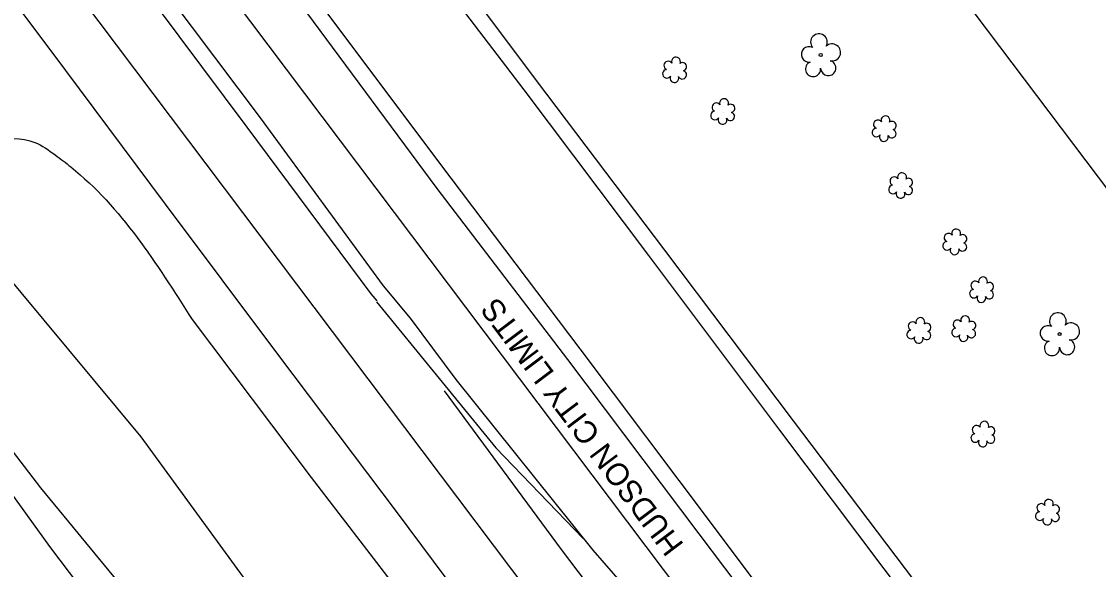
# Model space of a CAD drawing. Extents: x 1262092 to 1264624, y 774970 to 778314.
# Drawn here: x 1264127.3 to 1264367.4, y 775381.8 to 775504 of the extents above; entities that cross this region are included whole.
import ezdxf

# ---------------------------------------------------------------- set-up
doc = ezdxf.new("R2010")
doc.units = 0
for name, color, linetype in [('Exist Boundary City Limits', 7, 'Continuous'), ('Exist Boundary City Limits Text', 7, 'Continuous'), ('Exist Horizontal Alignment', 7, 'Continuous'), ('Exist Horizontal Alignment Tick Large', 7, 'Continuous'), ('Exist Horizontal Alignment Tick Small', 7, 'Continuous'), ('Exist Right of Way Line', 7, 'Continuous'), ('Exist Roads EOP', 7, 'Continuous'), ('Exist Roads EOT', 7, 'Continuous'), ('Exist Utilities Power UG Cable SUE LOS B', 7, 'Continuous'), ('Exist Utilities Telephone UG FO SUE LOS B', 7, 'Continuous'), ('Exist Utilities Water UG Line SUE LOS B', 7, 'Continuous')]:
    doc.layers.add(name, color=color, linetype=linetype)

msp = doc.modelspace()

# ---------------------------------------------------------------- linework, layer by layer
at = {"layer": 'Exist Boundary City Limits'}
msp.add_line((1264481.92, 775101.04), (1263870.58, 775912.68), dxfattribs=at)
at = {"layer": 'Exist Horizontal Alignment'}
msp.add_line((1264460.35, 775084.79), (1262255.05, 778012.66), dxfattribs=at)
at = {"layer": 'Exist Horizontal Alignment Tick Large'}
for p, q in [((1264272.98, 775493.05), (1264272.98, 775493.05)), ((1264283.7, 775483.77), (1264283.7, 775483.77)), ((1264319.7, 775479.94), (1264319.7, 775479.94)), ((1264323.39, 775467.25), (1264323.39, 775467.25)), ((1264335.46, 775454.68), (1264335.46, 775454.68)), ((1264341.43, 775444.01), (1264341.43, 775444.01)), ((1264327.45, 775434.93), (1264327.45, 775434.93)), ((1264337.46, 775435.34), (1264337.46, 775435.34)), ((1264341.73, 775411.81), (1264341.73, 775411.81)), ((1264356.13, 775394.38), (1264356.13, 775394.38))]:
    msp.add_line(p, q, dxfattribs=at)
for centre, radius, start, end in [((1264273.21, 775495.09), 0.99, 334.8391, 200.4717), ((1264271.5, 775494.18), 0.968, 35.8908, 245.4216), ((1264274.65, 775493.92), 0.929, 284.4567, 126.0861), ((1264271.18, 775492.35), 0.955, 95.1099, 327.9534), ((1264272.85, 775491.37), 0.984, 151.2797, 21.387), ((1264274.62, 775492.12), 0.937, 204.9913, 73.4601), ((1264283.93, 775485.81), 0.99, 334.8391, 200.4717), ((1264281.9, 775483.06), 0.955, 95.1099, 327.9534), ((1264282.22, 775484.89), 0.968, 35.8908, 245.4216), ((1264285.38, 775484.63), 0.929, 284.4567, 126.0861), ((1264283.58, 775482.08), 0.984, 151.2797, 21.387), ((1264285.34, 775482.84), 0.937, 204.9913, 73.4601), ((1264318.22, 775481.07), 0.968, 35.8908, 245.4216), ((1264319.93, 775481.98), 0.99, 334.8391, 200.4717), ((1264321.38, 775480.81), 0.929, 284.4567, 126.0861), ((1264317.9, 775479.24), 0.955, 95.1099, 327.9534), ((1264321.34, 775479.01), 0.937, 204.9913, 73.4601), ((1264319.57, 775478.26), 0.984, 151.2797, 21.387), ((1264323.61, 775469.29), 0.99, 334.8391, 200.4717), ((1264321.59, 775466.55), 0.955, 95.1099, 327.9534), ((1264321.9, 775468.38), 0.968, 35.8908, 245.4216), ((1264325.02, 775466.33), 0.937, 204.9913, 73.4601), ((1264325.06, 775468.12), 0.929, 284.4567, 126.0861), ((1264323.26, 775465.57), 0.984, 151.2797, 21.387), ((1264335.69, 775456.72), 0.99, 334.8391, 200.4717), ((1264333.98, 775455.8), 0.968, 35.8908, 245.4216), ((1264337.14, 775455.55), 0.929, 284.4567, 126.0861), ((1264333.66, 775453.97), 0.955, 95.1099, 327.9534), ((1264335.34, 775452.99), 0.984, 151.2797, 21.387), ((1264337.1, 775453.75), 0.937, 204.9913, 73.4601), ((1264339.95, 775445.14), 0.968, 35.8908, 245.4216), ((1264341.66, 775446.05), 0.99, 334.8391, 200.4717), ((1264343.1, 775444.88), 0.929, 284.4567, 126.0861), ((1264339.63, 775443.31), 0.955, 95.1099, 327.9534), ((1264343.07, 775443.08), 0.937, 204.9913, 73.4601), ((1264341.3, 775442.33), 0.984, 151.2797, 21.387), ((1264337.69, 775437.38), 0.99, 334.8391, 200.4717), ((1264325.97, 775436.05), 0.968, 35.8908, 245.4216), ((1264327.68, 775436.97), 0.99, 334.8391, 200.4717), ((1264329.12, 775435.79), 0.929, 284.4567, 126.0861), ((1264335.97, 775436.47), 0.968, 35.8908, 245.4216), ((1264339.13, 775436.21), 0.929, 284.4567, 126.0861), ((1264325.65, 775434.22), 0.955, 95.1099, 327.9534), ((1264327.32, 775433.24), 0.984, 151.2797, 21.387), ((1264329.09, 775434), 0.937, 204.9913, 73.4601), ((1264335.66, 775434.64), 0.955, 95.1099, 327.9534), ((1264337.33, 775433.66), 0.984, 151.2797, 21.387), ((1264339.09, 775434.41), 0.937, 204.9913, 73.4601), ((1264341.96, 775413.85), 0.99, 334.8391, 200.4717), ((1264339.93, 775411.11), 0.955, 95.1099, 327.9534), ((1264340.24, 775412.94), 0.968, 35.8908, 245.4216), ((1264343.4, 775412.68), 0.929, 284.4567, 126.0861), ((1264341.6, 775410.13), 0.984, 151.2797, 21.387), ((1264343.36, 775410.88), 0.937, 204.9913, 73.4601), ((1264354.65, 775395.51), 0.968, 35.8908, 245.4216), ((1264356.36, 775396.42), 0.99, 334.8391, 200.4717), ((1264357.8, 775395.25), 0.929, 284.4567, 126.0861), ((1264354.33, 775393.68), 0.955, 95.1099, 327.9534), ((1264356, 775392.7), 0.984, 151.2797, 21.387), ((1264357.77, 775393.45), 0.937, 204.9913, 73.4601)]:
    msp.add_arc(centre, radius, start, end, dxfattribs=at)
at = {"layer": 'Exist Horizontal Alignment Tick Small'}
for p, q in [((1264305.47, 775496.54), (1264305.47, 775496.54)), ((1264358.75, 775434.3), (1264358.75, 775434.3))]:
    msp.add_line(p, q, dxfattribs=at)
for centre in [(1264305.47, 775496.54), (1264358.75, 775434.3)]:
    msp.add_circle(centre, 0.326, dxfattribs=at)
for centre, radius, start, end in [((1264305.09, 775499.41), 1.86, 330.1651, 219.7134), ((1264302.87, 775496.69), 1.73, 62.6636, 279.3457), ((1264308.02, 775497.12), 1.9, 257.1011, 134.1999), ((1264303.77, 775493.41), 1.69, 111.5671, 6.231), ((1264307.15, 775493.64), 1.7, 181.2822, 74.56), ((1264358.36, 775437.18), 1.86, 330.1651, 219.7134), ((1264356.14, 775434.46), 1.73, 62.6636, 279.3457), ((1264361.3, 775434.89), 1.9, 257.1011, 134.1999), ((1264357.04, 775431.18), 1.69, 111.5671, 6.231), ((1264360.42, 775431.4), 1.7, 181.2822, 74.56)]:
    msp.add_arc(centre, radius, start, end, dxfattribs=at)
at = {"layer": 'Exist Right of Way Line'}
msp.add_line((1263590.4, 776500.74), (1264585.76, 775179.25), dxfattribs=at)
at = {"layer": 'Exist Roads EOP'}
for points in [[(1263928.62, 775926.46), (1263957.2, 775888.94), (1263984.37, 775849.97), (1264009.69, 775812.65), (1264036.52, 775773.35), (1264061.61, 775736.64), (1264089.12, 775695.12), (1264113.81, 775661.2), (1264140.49, 775625.83), (1264158.69, 775601.4), (1264188.06, 775562.53), (1264215.32, 775526.57), (1264242.02, 775490.86), (1264270.63, 775453.04), (1264299.34, 775414.94), (1264328.5, 775376.44), (1264356.79, 775338.17)], [(1263989.03, 775736.19), (1264015.83, 775700.49), (1264044.86, 775662.16), (1264072.94, 775625.89), (1264099.82, 775589.65), (1264127.93, 775552.1), (1264155.14, 775516.26), (1264180.47, 775482.54), (1264207.92, 775445.04), (1264213.92, 775437.85)], [(1264133.95, 775582.22), (1264162.45, 775543.56), (1264190.8, 775506.04), (1264219.88, 775466.74), (1264249.04, 775428.62), (1264278.29, 775389.75), (1264306.94, 775351.8), (1264336.28, 775312.74), (1264359.67, 775281.44), (1264366.76, 775271.73)], [(1264165.32, 775437.52), (1264191.9, 775402.28), (1264216.55, 775370.22), (1264243.85, 775333.7), (1264269.65, 775299.56), (1264295.65, 775264.58)], [(1264362.38, 775256.26), (1264341.8, 775283.01), (1264314.54, 775315.65), (1264283.95, 775352.55), (1264254.78, 775386.12), (1264224.19, 775424.16), (1264214.01, 775437.85)]]:
    msp.add_lwpolyline(points, dxfattribs=at)
msp.add_spline([(1264086.81, 775466.65), (1264091.31, 775469.51), (1264102.73, 775475.22), (1264111.91, 775477.39), (1264120.66, 775477.89), (1264130.22, 775477.03), (1264134.8, 775474.26), (1264138.29, 775471.59), (1264165.32, 775437.52)], degree=3, dxfattribs=at)
at = {"layer": 'Exist Roads EOT'}
for points in [[(1264446.09, 775083.45), (1264419.18, 775119.01), (1264392.54, 775154.06), (1264369.93, 775183.78), (1264343.71, 775218.57), (1264317, 775253.46), (1264292.67, 775285.65), (1264265.72, 775321.45), (1264237.79, 775358.61), (1264211.14, 775394.4), (1264184.66, 775429.54), (1264159.42, 775463.25), (1264133.92, 775497.47), (1264108.52, 775531.19), (1264082.14, 775566.55), (1264057.31, 775599.4), (1264024.24, 775643.38), (1263996.61, 775679.88), (1263968.79, 775716.67), (1263941.99, 775752.17)], [(1263986.52, 775734.29), (1264013.59, 775698.59), (1264042.53, 775660.51), (1264070.23, 775623.69), (1264096.97, 775588.25), (1264125.47, 775550.21), (1264152.28, 775514.35), (1264177.51, 775480.42), (1264205.19, 775443.24), (1264206.48, 775441.72)], [(1264059.51, 775735.12), (1264085.98, 775693.36), (1264110.99, 775658.57), (1264137.48, 775623.56), (1264156.04, 775598.9), (1264184.87, 775560.3), (1264212.27, 775524.15), (1264239.26, 775488.75), (1264267.11, 775451.81), (1264296.26, 775412.89), (1264325.39, 775374.15), (1264353.83, 775336.07), (1264380.48, 775300.79), (1264393.09, 775284.6)], [(1264136.41, 775584.13), (1264164.82, 775546.18), (1264193.7, 775508.14), (1264223.03, 775469.1), (1264251.78, 775430.99), (1264281.29, 775391.78), (1264309.55, 775354.05), (1264338.76, 775315.15), (1264363.95, 775281.81), (1264366.92, 775277.77)], [(1264206.44, 775441.5), (1264233.07, 775408.96), (1264252.48, 775388.73)], [(1264358.85, 775239.33), (1264331.63, 775275.17), (1264306.07, 775309.07), (1264277.17, 775347.3), (1264247.65, 775386.28), (1264221.61, 775421.65)]]:
    msp.add_lwpolyline(points, dxfattribs=at)
at = {"layer": 'Exist Utilities Power UG Cable SUE LOS B'}
msp.add_lwpolyline([(1264395.36, 775040.74), (1264370.8, 775076.36), (1264340.19, 775112.15), (1264308.39, 775149.99), (1264277.8, 775188.45), (1264254.82, 775218.46), (1264230.51, 775255.61), (1264208, 775290.17), (1264185.34, 775318.09), (1264158.04, 775354.59), (1264133.61, 775386.92), (1264107.25, 775423.32), (1264089.56, 775447.66), (1264061.08, 775477.65), (1264037.85, 775505.73), (1264032.45, 775511.96), (1264026.57, 775514.09), (1263970.61, 775511.19)], dxfattribs=at)
at = {"layer": 'Exist Utilities Telephone UG FO SUE LOS B'}
msp.add_lwpolyline([(1264412.43, 775054.27), (1264383.09, 775084.33), (1264350.27, 775127.37), (1264319.47, 775167.42), (1264288.52, 775206.2), (1264253.33, 775248.38), (1264233.02, 775276.08), (1264197.49, 775318.53), (1264165.2, 775359.15), (1264131.6, 775400.04), (1264102.3, 775438.18), (1264079.45, 775463.73), (1264046.01, 775506.17), (1264034.16, 775523.07), (1264026.26, 775546.1), (1264015.26, 775566.11), (1263989.3, 775607.52), (1263955.25, 775658.94), (1263921.26, 775710.27), (1263888.91, 775754.45), (1263860.31, 775793.96), (1263832.43, 775832.72), (1263818.26, 775866.25), (1263816.28, 775877)], dxfattribs=at)
at = {"layer": 'Exist Utilities Water UG Line SUE LOS B'}
msp.add_lwpolyline([(1264262.47, 775052.4), (1264270.03, 775057.49), (1264308.25, 775083.86), (1264311.99, 775091.01), (1264333.07, 775106.94), (1264365.39, 775127.89), (1264356.78, 775138.68), (1264342.07, 775157.58), (1264315.02, 775194.18), (1264289.27, 775228.94), (1264261.35, 775265.49), (1264234.66, 775298.88), (1264204.95, 775340.41), (1264179.39, 775376.51), (1264153.98, 775411.4), (1264121.66, 775450.17), (1264092.98, 775486.7), (1264069.57, 775517.58), (1264043.23, 775551.19), (1264018.68, 775582.59), (1263995.06, 775614.62), (1263975.68, 775643.74), (1263951.8, 775677.27), (1263925.33, 775714.09)], dxfattribs=at)

# ---------------------------------------------------------------- texts
at = {"layer": 'Exist Boundary City Limits Text'}
msp.add_text('HUDSON CITY LIMITS', height=5, rotation=126.9874, dxfattribs=at).set_placement((1264275.11, 775387.32))

doc.saveas('drawing.dxf')
